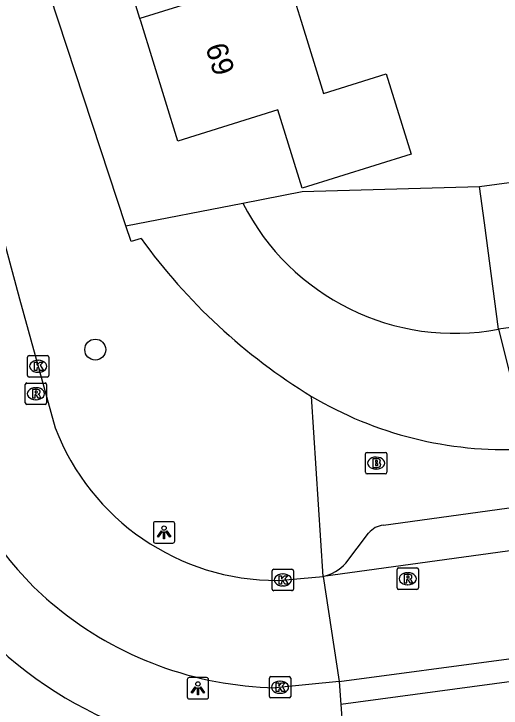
# Model space of a CAD drawing. Extents: x 159053 to 160041, y 380450 to 381422.
# Drawn here: x 159530.94 to 159553.7, y 380967.93 to 381000.34 of the extents above; entities that cross this region are included whole.
import ezdxf

# ---------------------------------------------------------------- set-up
doc = ezdxf.new("R2010")
doc.units = 0
for name, color, linetype in [('IMGEO_Boom', 7, 'Continuous'), ('IMGEO_Brandkraan', 7, 'Continuous'), ('IMGEO_Groenvoorziening', 7, 'Continuous'), ('IMGEO_Kolk', 7, 'Continuous'), ('IMGEO_Lichtpunt', 7, 'Continuous'), ('IMGEO_Pand', 7, 'Continuous'), ('IMGEO_Pand_nummerreeks', 7, 'Continuous'), ('IMGEO_Rijbaan_lokaal_open', 7, 'Continuous'), ('IMGEO_Rioolput', 7, 'Continuous'), ('IMGEO_Voetpad_op_trap', 7, 'Continuous'), ('IMGEO_Voetpad_open', 7, 'Continuous')]:
    doc.layers.add(name, color=color, linetype=linetype)

msp = doc.modelspace()

# ---------------------------------------------------------------- linework, layer by layer
at = {"layer": 'IMGEO_Boom'}
msp.add_circle((159534.742, 380984.664), 0.489, dxfattribs=at)
at = {"layer": 'IMGEO_Brandkraan'}
for p, q in [((159547.366, 380978.94), (159547.366, 380979.792)), ((159547.441, 380979.866), (159548.293, 380979.866)), ((159548.367, 380979.792), (159548.367, 380978.94)), ((159547.854, 380979.646), (159547.879, 380979.646)), ((159547.877, 380979.086), (159547.852, 380979.086)), ((159548.293, 380978.866), (159547.441, 380978.866))]:
    msp.add_line(p, q, dxfattribs=at)
for points in [[(159547.366, 380978.94), (159547.366, 380979.792)], [(159547.441, 380979.866), (159548.293, 380979.866)], [(159548.367, 380979.792), (159548.367, 380978.94)], [(159547.714, 380979.566), (159547.714, 380979.166), (159547.927, 380979.166)], [(159547.945, 380979.566), (159547.714, 380979.566)], [(159547.893, 380979.485), (159547.839, 380979.485), (159547.839, 380979.409)], [(159547.839, 380979.409), (159547.892, 380979.409)], [(159547.901, 380979.333), (159547.839, 380979.333), (159547.839, 380979.252)], [(159547.839, 380979.252), (159547.901, 380979.252)], [(159548.293, 380978.866), (159547.441, 380978.866)]]:
    msp.add_lwpolyline(points, dxfattribs=at)
for centre, radius, start, end in [((159547.443, 380979.79), 0.0765, 91.552, 178.448), ((159547.443, 380979.79), 0.0765, 91.552, 178.448), ((159548.291, 380979.79), 0.0765, 1.552, 88.448), ((159548.291, 380979.79), 0.0765, 1.552, 88.448), ((159547.894, 380979.447), 0.0379, 267.8285, 90.9355), ((159547.949, 380979.421), 0.145, 59.4692, 91.5367), ((159547.974, 380979.468), 0.0922, 285.5137, 58.1501), ((159547.902, 380979.292), 0.0404, 269.8759, 90.5077), ((159547.933, 380979.417), 0.251, 268.6676, 293.5347), ((159547.979, 380979.276), 0.105, 301.3115, 78.989), ((159547.443, 380978.942), 0.0765, 181.552, 268.448), ((159547.443, 380978.942), 0.0765, 181.552, 268.448), ((159548.291, 380978.942), 0.0765, 271.552, 358.448), ((159548.291, 380978.942), 0.0765, 271.552, 358.448)]:
    msp.add_arc(centre, radius, start, end, dxfattribs=at)
for centre, major_axis, ratio, start_param, end_param in [((159547.853, 380979.366), (-0.387, 0.002), 0.722429, 4.712389, 7.853982), ((159547.878, 380979.366), (-0.39, 0.002), 0.717154, 1.570796, 4.712389)]:
    msp.add_ellipse(centre, major_axis=major_axis, ratio=ratio, start_param=start_param, end_param=end_param, dxfattribs=at)
at = {"layer": 'IMGEO_Groenvoorziening'}
for points in [[(159541.635, 380991.506), (159544.413, 380992.044), (159552.695, 380992.276)], [(159536.175, 380990.447), (159541.635, 380991.506)], [(159553.589, 380985.62), (159554.983, 380980.049)]]:
    msp.add_lwpolyline(points, dxfattribs=at)
msp.add_arc((159551.529, 380996.518), 11.091, 206.8671, 280.7027, dxfattribs=at)
at = {"layer": 'IMGEO_Kolk'}
for p, q in [((159531.575, 380983.459), (159531.575, 380984.311)), ((159531.65, 380984.385), (159532.502, 380984.385)), ((159532.576, 380984.311), (159532.576, 380983.459)), ((159532.063, 380984.165), (159532.088, 380984.165)), ((159532.086, 380983.605), (159532.061, 380983.605)), ((159532.502, 380983.385), (159531.65, 380983.385)), ((159543.006, 380973.486), (159543.006, 380974.338)), ((159543.081, 380974.412), (159543.933, 380974.412)), ((159544.007, 380974.338), (159544.007, 380973.486)), ((159543.494, 380974.192), (159543.519, 380974.192)), ((159543.517, 380973.632), (159543.492, 380973.632)), ((159543.933, 380973.412), (159543.081, 380973.412)), ((159542.95, 380969.402), (159543.802, 380969.402)), ((159542.875, 380968.476), (159542.875, 380969.328)), ((159543.363, 380969.182), (159543.388, 380969.182)), ((159543.876, 380969.328), (159543.876, 380968.476)), ((159543.802, 380968.402), (159542.95, 380968.402)), ((159543.386, 380968.622), (159543.361, 380968.622))]:
    msp.add_line(p, q, dxfattribs=at)
for points in [[(159531.575, 380983.459), (159531.575, 380984.311)], [(159531.65, 380984.385), (159532.502, 380984.385)], [(159532.576, 380984.311), (159532.576, 380983.459)], [(159531.896, 380984.085), (159532.019, 380984.085), (159532.019, 380983.934), (159532.149, 380984.085), (159532.313, 380984.085), (159532.167, 380983.934), (159532.32, 380983.685), (159532.168, 380983.685), (159532.083, 380983.849), (159532.019, 380983.782), (159532.019, 380983.685), (159531.896, 380983.685), (159531.896, 380984.085)], [(159532.502, 380983.385), (159531.65, 380983.385)], [(159543.006, 380973.486), (159543.006, 380974.338)], [(159543.081, 380974.412), (159543.933, 380974.412)], [(159544.007, 380974.338), (159544.007, 380973.486)], [(159543.327, 380974.112), (159543.45, 380974.112), (159543.45, 380973.961), (159543.58, 380974.112), (159543.744, 380974.112), (159543.598, 380973.961), (159543.751, 380973.712), (159543.599, 380973.712), (159543.514, 380973.876), (159543.45, 380973.809), (159543.45, 380973.712), (159543.327, 380973.712), (159543.327, 380974.112)], [(159543.933, 380973.412), (159543.081, 380973.412)], [(159542.95, 380969.402), (159543.802, 380969.402)], [(159542.875, 380968.476), (159542.875, 380969.328)], [(159543.196, 380969.102), (159543.319, 380969.102), (159543.319, 380968.951), (159543.449, 380969.102), (159543.613, 380969.102), (159543.467, 380968.951), (159543.62, 380968.702), (159543.468, 380968.702), (159543.383, 380968.866), (159543.319, 380968.799), (159543.319, 380968.702), (159543.196, 380968.702), (159543.196, 380969.102)], [(159543.876, 380969.328), (159543.876, 380968.476)], [(159543.802, 380968.402), (159542.95, 380968.402)]]:
    msp.add_lwpolyline(points, dxfattribs=at)
for centre, start, end in [((159531.652, 380984.309), 91.552, 178.448), ((159531.652, 380984.309), 91.552, 178.448), ((159532.5, 380984.309), 1.552, 88.448), ((159532.5, 380984.309), 1.552, 88.448), ((159531.652, 380983.461), 181.552, 268.448), ((159531.652, 380983.461), 181.552, 268.448), ((159532.5, 380983.461), 271.552, 358.448), ((159532.5, 380983.461), 271.552, 358.448), ((159543.083, 380974.336), 91.552, 178.448), ((159543.083, 380974.336), 91.552, 178.448), ((159543.931, 380974.336), 1.552, 88.448), ((159543.931, 380974.336), 1.552, 88.448), ((159543.083, 380973.488), 181.552, 268.448), ((159543.083, 380973.488), 181.552, 268.448), ((159543.931, 380973.488), 271.552, 358.448), ((159543.931, 380973.488), 271.552, 358.448), ((159542.952, 380969.326), 91.552, 178.448), ((159542.952, 380969.326), 91.552, 178.448), ((159543.8, 380969.326), 1.552, 88.448), ((159543.8, 380969.326), 1.552, 88.448), ((159542.952, 380968.478), 181.552, 268.448), ((159542.952, 380968.478), 181.552, 268.448), ((159543.8, 380968.478), 271.552, 358.448), ((159543.8, 380968.478), 271.552, 358.448)]:
    msp.add_arc(centre, 0.0765, start, end, dxfattribs=at)
for centre, major_axis, ratio, start_param, end_param in [((159532.062, 380983.885), (-0.387, 0.002), 0.722429, 4.712389, 7.853982), ((159532.087, 380983.885), (-0.39, 0.002), 0.717154, 1.570796, 4.712389), ((159543.493, 380973.912), (-0.387, 0.002), 0.722429, 4.712389, 7.853982), ((159543.518, 380973.912), (-0.39, 0.002), 0.717154, 1.570796, 4.712389), ((159543.362, 380968.902), (-0.387, 0.002), 0.722429, 4.712389, 7.853982), ((159543.387, 380968.902), (-0.39, 0.002), 0.717154, 1.570796, 4.712389)]:
    msp.add_ellipse(centre, major_axis=major_axis, ratio=ratio, start_param=start_param, end_param=end_param, dxfattribs=at)
at = {"layer": 'IMGEO_Lichtpunt'}
for p, q in [((159537.457, 380976.537), (159537.457, 380975.73)), ((159537.457, 380976.537), (159537.457, 380975.73)), ((159538.359, 380976.632), (159537.551, 380976.632)), ((159538.359, 380976.632), (159537.551, 380976.632)), ((159538.453, 380975.73), (159538.453, 380976.537)), ((159538.453, 380975.73), (159538.453, 380976.537)), ((159537.551, 380975.636), (159538.359, 380975.636)), ((159537.551, 380975.636), (159538.359, 380975.636)), ((159539.942, 380969.354), (159539.134, 380969.354)), ((159539.942, 380969.354), (159539.134, 380969.354)), ((159539.04, 380969.259), (159539.04, 380968.452)), ((159539.04, 380969.259), (159539.04, 380968.452)), ((159540.036, 380968.452), (159540.036, 380969.259)), ((159540.036, 380968.452), (159540.036, 380969.259)), ((159539.134, 380968.358), (159539.942, 380968.358)), ((159539.134, 380968.358), (159539.942, 380968.358))]:
    msp.add_line(p, q, dxfattribs=at)
for points in [[(159537.831, 380976.201), (159537.87, 380976.173), (159537.682, 380975.911), (159537.644, 380975.938), (159537.831, 380976.201)], [(159537.933, 380976.153), (159537.98, 380976.153), (159537.98, 380975.831), (159537.933, 380975.831), (159537.933, 380976.153)], [(159538.043, 380976.173), (159538.081, 380976.2), (159538.268, 380975.938), (159538.229, 380975.91), (159538.043, 380976.173)], [(159539.414, 380968.923), (159539.453, 380968.895), (159539.265, 380968.633), (159539.227, 380968.66), (159539.414, 380968.923)], [(159539.516, 380968.875), (159539.563, 380968.875), (159539.563, 380968.553), (159539.516, 380968.553), (159539.516, 380968.875)], [(159539.626, 380968.895), (159539.664, 380968.922), (159539.851, 380968.66), (159539.812, 380968.632), (159539.626, 380968.895)]]:
    msp.add_lwpolyline(points, dxfattribs=at)
for centre in [(159537.956, 380976.335), (159539.539, 380969.057)]:
    msp.add_circle(centre, 0.0994, dxfattribs=at)
for centre, start, end in [((159537.551, 380976.537), 90, 180), ((159537.551, 380976.537), 90, 180), ((159538.359, 380976.537), 0, 90), ((159538.359, 380976.537), 0, 90), ((159537.551, 380975.73), 180, 270), ((159537.551, 380975.73), 180, 270), ((159538.359, 380975.73), 270, 0), ((159538.359, 380975.73), 270, 360), ((159539.134, 380969.259), 90, 180), ((159539.134, 380969.259), 90, 180), ((159539.942, 380969.259), 0, 90), ((159539.942, 380969.259), 0, 90), ((159539.134, 380968.452), 180, 270), ((159539.134, 380968.452), 180, 270), ((159539.942, 380968.452), 270, 0), ((159539.942, 380968.452), 270, 360)]:
    msp.add_arc(centre, 0.0946, start, end, dxfattribs=at)
at = {"layer": 'IMGEO_Pand'}
for points in [[(159536.832, 381000.127), (159535.107, 381005.712)], [(159543.663, 381002.253), (159544.363, 381000), (159545.411, 380996.628), (159548.335, 380997.538), (159549.501, 380993.789), (159544.408, 380992.205), (159543.273, 380995.852), (159538.601, 380994.398), (159536.871, 381000), (159536.832, 381000.127)], [(159543.663, 381002.253), (159536.832, 381000.127)], [(159552.695, 380992.276), (159559.053, 380993.13)], [(159553.589, 380985.62), (159552.923, 380990.576), (159552.695, 380992.276)], [(159559.948, 380986.474), (159553.589, 380985.62)]]:
    msp.add_lwpolyline(points, dxfattribs=at)
at = {"layer": 'IMGEO_Rijbaan_lokaal_open'}
for points in [[(159529.618, 380992.905), (159529.946, 380991.677), (159531.206, 380987.032), (159532.871, 380981.007)], [(159573.269, 380977.897), (159545.388, 380974.074)], [(159543.266, 380973.891), (159545.388, 380974.074)], [(159545.388, 380974.074), (159546.141, 380969.164)], [(159546.141, 380969.164), (159554.06, 380970.237)], [(159546.141, 380969.164), (159543.145, 380968.88)]]:
    msp.add_lwpolyline(points, dxfattribs=at)
for centre, radius, start, end in [((159543.221, 380984.975), 11.084, 200.9779, 270.2341), ((159542.229, 380984.102), 14.758, 196.4053, 230.7707), ((159543.507, 380985.616), 16.74, 230.6562, 268.7594)]:
    msp.add_arc(centre, radius, start, end, dxfattribs=at)
at = {"layer": 'IMGEO_Rioolput'}
for p, q in [((159531.468, 380982.18), (159531.468, 380983.032)), ((159531.543, 380983.106), (159532.395, 380983.106)), ((159532.469, 380983.032), (159532.469, 380982.18)), ((159531.956, 380982.886), (159531.981, 380982.886)), ((159531.979, 380982.326), (159531.954, 380982.326)), ((159532.395, 380982.106), (159531.543, 380982.106)), ((159548.842, 380973.544), (159548.842, 380974.396)), ((159548.917, 380974.47), (159549.769, 380974.47)), ((159549.33, 380974.25), (159549.355, 380974.25)), ((159549.843, 380974.396), (159549.843, 380973.544)), ((159549.353, 380973.69), (159549.328, 380973.69)), ((159549.769, 380973.47), (159548.917, 380973.47))]:
    msp.add_line(p, q, dxfattribs=at)
for points in [[(159531.468, 380982.18), (159531.468, 380983.032)], [(159531.543, 380983.106), (159532.395, 380983.106)], [(159532.469, 380983.032), (159532.469, 380982.18)], [(159532.057, 380982.804), (159531.805, 380982.806), (159531.805, 380982.406)], [(159531.983, 380982.725), (159531.929, 380982.725), (159531.929, 380982.644)], [(159531.929, 380982.644), (159531.981, 380982.644)], [(159531.805, 380982.406), (159531.929, 380982.406), (159531.929, 380982.568), (159531.94, 380982.568)], [(159531.987, 380982.539), (159532.058, 380982.406), (159532.198, 380982.406), (159532.133, 380982.532)], [(159532.395, 380982.106), (159531.543, 380982.106)], [(159548.842, 380973.544), (159548.842, 380974.396)], [(159548.917, 380974.47), (159549.769, 380974.47)], [(159549.843, 380974.396), (159549.843, 380973.544)], [(159549.431, 380974.168), (159549.179, 380974.17), (159549.179, 380973.77)], [(159549.179, 380973.77), (159549.303, 380973.77), (159549.303, 380973.932), (159549.314, 380973.932)], [(159549.357, 380974.089), (159549.303, 380974.089), (159549.303, 380974.008)], [(159549.303, 380974.008), (159549.355, 380974.008)], [(159549.361, 380973.903), (159549.432, 380973.77), (159549.572, 380973.77), (159549.507, 380973.896)], [(159549.769, 380973.47), (159548.917, 380973.47)]]:
    msp.add_lwpolyline(points, dxfattribs=at)
for centre, radius, start, end in [((159531.545, 380983.03), 0.0765, 91.552, 178.448), ((159531.545, 380983.03), 0.0765, 91.552, 178.448), ((159532.393, 380983.03), 0.0765, 1.552, 88.448), ((159532.393, 380983.03), 0.0765, 1.552, 88.448), ((159531.965, 380982.833), 0.19, 274.7715, 282.9687), ((159531.989, 380982.629), 0.0964, 77.0061, 93.1865), ((159532.003, 380982.686), 0.0378, 276.6634, 79.6772), ((159532.056, 380982.694), 0.109, 350.3612, 89.416), ((159532.054, 380982.694), 0.112, 277.5842, 350.9817), ((159531.939, 380982.515), 0.0533, 26.0293, 88.6989), ((159532.038, 380982.479), 0.108, 29.5134, 73.7905), ((159531.545, 380982.182), 0.0765, 181.552, 268.448), ((159531.545, 380982.182), 0.0765, 181.552, 268.448), ((159532.393, 380982.182), 0.0765, 271.552, 358.448), ((159532.393, 380982.182), 0.0765, 271.552, 358.448), ((159548.919, 380974.394), 0.0765, 91.552, 178.448), ((159548.919, 380974.394), 0.0765, 91.552, 178.448), ((159549.767, 380974.394), 0.0765, 1.552, 88.448), ((159549.767, 380974.394), 0.0765, 1.552, 88.448), ((159549.313, 380973.879), 0.0533, 26.0293, 88.6989), ((159549.339, 380974.197), 0.19, 274.7715, 282.9687), ((159549.363, 380973.993), 0.0964, 77.0061, 93.1865), ((159549.377, 380974.05), 0.0378, 276.6634, 79.6772), ((159549.43, 380974.058), 0.109, 350.3612, 89.416), ((159549.428, 380974.058), 0.112, 277.5842, 350.9817), ((159549.412, 380973.843), 0.108, 29.5134, 73.7905), ((159548.919, 380973.546), 0.0765, 181.552, 268.448), ((159548.919, 380973.546), 0.0765, 181.552, 268.448), ((159549.767, 380973.546), 0.0765, 271.552, 358.448), ((159549.767, 380973.546), 0.0765, 271.552, 358.448)]:
    msp.add_arc(centre, radius, start, end, dxfattribs=at)
for centre, major_axis, ratio, start_param, end_param in [((159531.955, 380982.606), (-0.387, 0.002), 0.722429, 4.712389, 7.853982), ((159531.98, 380982.606), (-0.39, 0.002), 0.717154, 1.570796, 4.712389), ((159549.329, 380973.97), (-0.387, 0.002), 0.722429, 4.712389, 7.853982), ((159549.354, 380973.97), (-0.39, 0.002), 0.717154, 1.570796, 4.712389)]:
    msp.add_ellipse(centre, major_axis=major_axis, ratio=ratio, start_param=start_param, end_param=end_param, dxfattribs=at)
at = {"layer": 'IMGEO_Voetpad_op_trap'}
msp.add_lwpolyline([(159554.204, 380969.164), (159546.217, 380968.102)], dxfattribs=at)
at = {"layer": 'IMGEO_Voetpad_open'}
for points in [[(159536.175, 380990.447), (159531.838, 381003.607), (159526.805, 381019.287)], [(159536.881, 380989.854), (159536.416, 380989.716), (159536.175, 380990.447)], [(159545.388, 380974.074), (159544.844, 380982.483)], [(159548.207, 380976.467), (159571.136, 380979.631)], [(159546.445, 380974.692), (159547.513, 380976.102)], [(159546.141, 380969.164), (159546.217, 380968.102)], [(159546.217, 380968.102), (159546.368, 380965.982)]]:
    msp.add_lwpolyline(points, dxfattribs=at)
for centre, radius, start, end in [((159559.27, 381006.055), 27.636, 215.8891, 238.5328), ((159553.913, 380997.773), 17.777, 239.325, 272.6107), ((159548.299, 380975.45), 1.021, 95.1622, 140.3209), ((159544.908, 380976.108), 2.09, 283.2818, 317.3456), ((159543.154, 380984.889), 19.178, 227.763, 279.6483)]:
    msp.add_arc(centre, radius, start, end, dxfattribs=at)

# ---------------------------------------------------------------- texts
at = {"layer": 'IMGEO_Pand_nummerreeks'}
msp.add_text('69', height=1, rotation=287.1617, dxfattribs=at).set_placement((159539.88, 380998.795))

doc.saveas('drawing.dxf')
